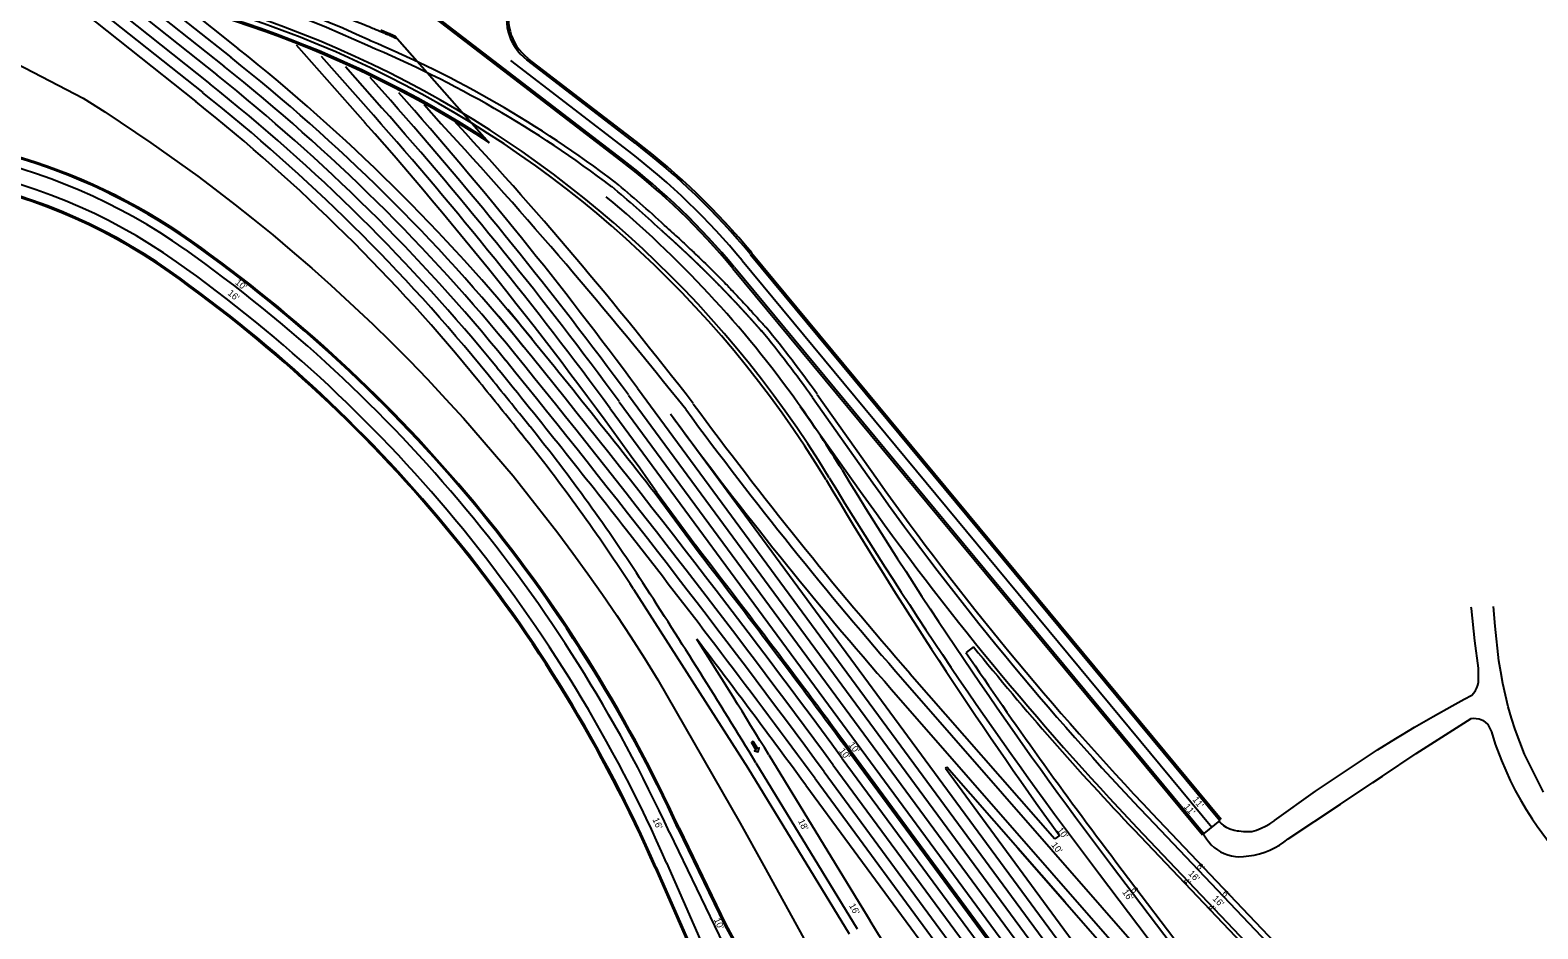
# Model space of a CAD drawing. Extents: x -5665 to 1997148, y 4 to 812485.
# Drawn here: x 1969615 to 1971217, y 796747 to 797701 of the extents above; entities that cross this region are included whole.
import ezdxf

# ---------------------------------------------------------------- set-up
doc = ezdxf.new("R2010")
doc.units = 0
for name, color, linetype in [('BR_CONCRETE', 7, 'Continuous'), ('RD_EX_RailRoad', 7, 'Continuous'), ('RD_EX_Road', 7, 'Continuous'), ('RD_PD_ALT1_TrvlWay', 7, 'Continuous'), ('RD_PD_Final_LnLine', 7, 'Continuous'), ('RD_PD_MedBWall', 7, 'Continuous'), ('RD_PD_PaveShd', 7, 'Continuous'), ('RD_SHT_TX', 7, 'Continuous'), ('RD_Sketch1', 7, 'Continuous')]:
    doc.layers.add(name, color=color, linetype=linetype)

msp = doc.modelspace()

# ---------------------------------------------------------------- linework, layer by layer
at = {"layer": 'BR_CONCRETE'}
for p, q in [((1970002.3, 797694.7), (1970102.7, 797581.1)), ((1970303.1, 796853.3), (1970352.7, 796750.9)), ((1970304.3, 796853.9), (1970353.9, 796751.4)), ((1970278.9, 796811.4), (1970358.4, 796629.6)), ((1970280, 796811.9), (1970359.6, 796630.2)), ((1970352.7, 796750.9), (1970407.3, 796650.9)), ((1970353.9, 796751.5), (1970408.4, 796651.5))]:
    msp.add_line(p, q, dxfattribs=at)
for centre, radius, start, end in [((1969482, 796626.9), 1177.6, 76.5407, 163.611), ((1969482, 796626.9), 1176, 76.5391, 163.611), ((1969482, 796626.9), 1140, 57.2466, 163.611), ((1969482, 796626.9), 1138.4, 56.954, 163.611), ((1969983.7, 797690), 10, 66.9788, 67.0375), ((1969987.6, 797699.2), 1.63, 67.0375, 67.0457), ((1969983.7, 797690), 11.6, 66.9788, 67.0375), ((1969424.5, 796964.6), 627.3, 54.7761, 131.4818), ((1969424.5, 796964.6), 626, 54.7761, 131.4818), ((1969424.5, 796964.6), 588, 54.7761, 157.246), ((1969424.5, 796964.6), 586.7, 54.7761, 157.246), ((1968885.8, 796201.6), 1560, 24.6943, 54.7761), ((1968885.8, 796201.6), 1561.3, 24.6943, 54.7761), ((1968885.8, 796201.6), 1520.7, 23.6393, 54.7761), ((1968885.8, 796201.6), 1522, 23.6393, 54.7761)]:
    msp.add_arc(centre, radius, start, end, dxfattribs=at)
for points in [[(1969930.9, 797721.6), (1969931.2, 797721.5), (1969931.5, 797721.4), (1969932, 797721.2), (1969932.3, 797721.1), (1969933.2, 797720.7), (1969935, 797720.1), (1969939.2, 797718.5), (1969947.5, 797715.4), (1969959.4, 797710.8), (1969971.2, 797706.1), (1969979.4, 797702.7), (1969983.5, 797701), (1969985.3, 797700.2), (1969986.1, 797699.8), (1969986.4, 797699.7), (1969987, 797699.5), (1969987.3, 797699.4), (1969987.6, 797699.2)], [(1969987.6, 797699.2), (1969987.9, 797699.1), (1969988.2, 797699), (1969988.8, 797698.7), (1969989.1, 797698.6), (1969989.9, 797698.2), (1969991.7, 797697.5), (1969995.8, 797695.7), (1970000.4, 797693.7), (1970003.8, 797692.2), (1970004.8, 797691.8)], [(1969988.2, 797700.7), (1969988.8, 797700.5), (1969989.4, 797700.2), (1969990.6, 797699.7), (1969991.2, 797699.5), (1969992.9, 797698.7), (1969996.4, 797697.2), (1969999.9, 797695.7), (1970002.3, 797694.7)]]:
    msp.add_open_spline(points, degree=3, dxfattribs=at)
at = {"layer": 'RD_EX_RailRoad'}
msp.add_lwpolyline([(1969600.3, 797665.2), (1969671.2, 797628.6), (1969694.2, 797613.9), (1969743.1, 797581.2), (1969793, 797545.6), (1969811, 797532.1), (1969832.7, 797515.3), (1969851.5, 797500.5), (1969872.6, 797483.3), (1969893.4, 797465.9), (1969914, 797448.1), (1969934.3, 797430), (1969979.1, 797388.5), (1969997.6, 797370.3), (1970017.4, 797350.3), (1970037, 797330.1), (1970056.2, 797309.5), (1970075.2, 797288.7), (1970127.9, 797227.7), (1970151.1, 797198.4), (1970158.9, 797188.5), (1970175.4, 797167.1), (1970191.6, 797145.5), (1970207.5, 797123.6), (1970223, 797101.5), (1970238.2, 797079.2), (1970253.1, 797056.7), (1970267.6, 797034), (1970281.8, 797011), (1970369.1, 796859), (1970394.2, 796813.5), (1970496.5, 796627.9)], dxfattribs=at)
at = {"layer": 'RD_EX_Road'}
for points in [[(1970877.7, 796861), (1970880.1, 796858.6), (1970882.7, 796856.4), (1970885.5, 796854.6), (1970888.6, 796853.1), (1970889.4, 796852.8), (1970894.1, 796851.5), (1970897, 796850.9), (1970898.9, 796850.6), (1970903.8, 796850.1), (1970908.6, 796849.9), (1970912.8, 796850.1), (1970917.8, 796851.6), (1970922.7, 796853.5), (1970927.4, 796855.7), (1970931.9, 796858.3), (1970936.2, 796861.2), (1970936.9, 796861.8), (1970980.2, 796893), (1971046.1, 796936.7), (1971046.3, 796936.8), (1971065.6, 796948.9), (1971072.8, 796953.2), (1971085.4, 796960.8), (1971105.3, 796972.3), (1971125.5, 796983.5), (1971138.4, 796990.4), (1971146.6, 796994.8), (1971148.7, 796997.1), (1971150.4, 796999.7), (1971151.8, 797002.5), (1971152.8, 797005.4), (1971153.4, 797008.5), (1971153.5, 797009.3), (1971153.4, 797023.5), (1971149.8, 797052.5), (1971146, 797086.9), (1971145.9, 797088.2)], [(1971222.4, 796891.9), (1971213, 796910.8), (1971202.4, 796932.1), (1971202.3, 796932.3), (1971192.4, 796958.4), (1971188.6, 796970.4), (1971185.1, 796982.5), (1971182.1, 796994.7), (1971179.4, 797007), (1971177.1, 797019.4), (1971175.2, 797031.2), (1971171.4, 797068.2), (1971169.4, 797088.9)], [(1970861.2, 796847.5), (1970863.8, 796843.4), (1970864.5, 796842.4), (1970866.7, 796839.4), (1970867, 796839.1), (1970869.7, 796836), (1970872.8, 796833.2), (1970876.1, 796830.7), (1970879.6, 796828.5), (1970883.3, 796826.7), (1970887.2, 796825.2), (1970891.2, 796824.1), (1970895.3, 796823.4), (1970898.1, 796823.3), (1970903.8, 796823.5), (1970909.6, 796824.1), (1970915.2, 796825.1), (1970920.9, 796826.4), (1970926.4, 796828.1), (1970931.7, 796830.3), (1970936.9, 796832.7), (1970942, 796835.5), (1970946.8, 796838.7), (1970951.4, 796842.2), (1971007, 796879.2), (1971041.3, 796902.1), (1971051.4, 796908.8), (1971087.2, 796932.8), (1971145.8, 796970), (1971148, 796970.2), (1971151.2, 796970.1), (1971154.3, 796969.7), (1971157.8, 796968.3), (1971160.7, 796966.2), (1971163.5, 796963.7), (1971167.5, 796956), (1971171.2, 796942.7), (1971177.8, 796925.4), (1971182.4, 796914.7), (1971187.3, 796904.1), (1971192.5, 796893.7), (1971198.1, 796883.5), (1971204.1, 796873.4), (1971210.4, 796863.6), (1971215.9, 796855.6), (1971244.7, 796816.7)]]:
    msp.add_lwpolyline(points, dxfattribs=at)
at = {"layer": 'RD_PD_ALT1_TrvlWay'}
for p, q in [((1970244.1, 797563.5), (1969975.7, 797769.5)), ((1969650.1, 797752.2), (1969798.3, 797634.4)), ((1969751.1, 797733.2), (1969828.2, 797672)), ((1969924.1, 797673.2), (1969979.7, 797610.4)), ((1970257.5, 797580.9), (1970142.5, 797669.2)), ((1970033.5, 797622), (1970051.7, 797601.4)), ((1970379.9, 797463.1), (1970878.6, 796861.8)), ((1970363, 797449.1), (1970861.7, 796847.8)), ((1970446.1, 797310.7), (1970510.2, 797220.3)), ((1970231.2, 797299.2), (1971104.3, 796114.9)), ((1970295.1, 797293.4), (1971172.6, 796103.1)), ((1970433, 797301.4), (1970497.1, 797211)), ((1970530.1, 797000.8), (1971103.9, 796345.5)), ((1970542.1, 797011.3), (1970931.8, 796566.4)), ((1970386, 796923), (1970493.6, 796746.7)), ((1970399.6, 796931.4), (1970507.2, 796755.1)), ((1970477.7, 796927.7), (1971068.8, 796125.9)), ((1970439.1, 796899.2), (1970686.6, 796563.5)), ((1970950.5, 796686.6), (1970791, 796854.1)), ((1970962.1, 796697.6), (1970802.6, 796865.2)), ((1970878.6, 796861.8), (1970861.7, 796847.8)), ((1970294.1, 796849.1), (1970387.5, 796656.1)), ((1970291, 796816.7), (1970370.6, 796635)), ((1970763.6, 796814.3), (1971082.9, 796393.9)), ((1970750.9, 796804.6), (1970931.8, 796566.4))]:
    msp.add_line(p, q, dxfattribs=at)
for centre, radius, start, end in [((1969482, 796626.9), 1166, 65.0802, 163.611), ((1969482, 796626.9), 1150, 31.3716, 163.611), ((1970176, 797712.9), 55, 156.731, 232.4907), ((1968569.2, 796087.2), 2024, 39.149, 51.5342), ((1969519.7, 796598.3), 1176.9, 52.7084, 67.3322), ((1968569.2, 796087.2), 1976, 39.149, 51.5342), ((1966609, 794629), 4500, 36.3977, 41.4938), ((1965926.6, 793804.9), 5606.2, 38.5451, 42.6249), ((1969424.5, 796964.6), 616, 54.7761, 150.713), ((1969794.2, 796977.3), 761, 39.6755, 52.4907), ((1969424.5, 796964.6), 600, 54.7761, 157.246), ((1969794.2, 796977.3), 739, 39.6755, 52.4907), ((1969482, 796626.9), 1178, 47.0463, 50.4066), ((1968885.8, 796201.6), 1550, 24.6902, 54.7761), ((1968885.8, 796201.6), 1534, 23.6393, 54.7761), ((1961201.8, 790089.5), 11524, 36.39766, 39.3518), ((1969482, 796626.9), 1182, 35.3463, 39.6755), ((1961201.8, 790089.5), 11476, 38.79674, 39.14904), ((1969482, 796626.9), 1166, 31.3716, 35.5262), ((1973840.1, 799899.7), 4400, 216.3977, 221.212), ((1973840.1, 799899.7), 4384, 216.3977, 221.212), ((1968587.2, 796026.8), 2000, 32.929, 38.7967), ((1974732.9, 799828.5), 5000, 211.3716, 217.212), ((1974732.9, 799828.5), 4984, 211.3716, 217.212), ((1973120.3, 799071.5), 3216, 215.3463, 223.5898), ((1973120.3, 799071.5), 3200, 215.3463, 223.5898), ((1963181.8, 792526), 8440, 31.39766, 32.92901), ((1963181.8, 792526), 8456, 31.39766, 32.37925), ((1958787.1, 788309.3), 14476, 36.3975, 37.16445), ((1972641.1, 798057.5), 2500, 210.9127, 216.3977)]:
    msp.add_arc(centre, radius, start, end, dxfattribs=at)
for points in [[(1970284.7, 797489.1), (1970285.2, 797488.6), (1970285.7, 797488.1), (1970286.2, 797487.7), (1970286.7, 797487.2), (1970287.2, 797486.8), (1970287.7, 797486.3), (1970288.2, 797485.9), (1970288.7, 797485.4), (1970289.3, 797485), (1970289.8, 797484.5), (1970290.3, 797484.1), (1970290.8, 797483.6), (1970291.3, 797483.1), (1970291.8, 797482.7), (1970292.3, 797482.2), (1970292.8, 797481.8), (1970293.3, 797481.3), (1970293.8, 797480.9), (1970294.3, 797480.4), (1970294.8, 797480), (1970295.3, 797479.5), (1970295.9, 797479), (1970296.4, 797478.6), (1970296.9, 797478.1), (1970297.4, 797477.7), (1970297.9, 797477.2), (1970298.4, 797476.7), (1970298.9, 797476.3), (1970299.4, 797475.8), (1970299.9, 797475.4), (1970300.4, 797474.9), (1970300.9, 797474.4), (1970301.4, 797474), (1970301.9, 797473.5), (1970302.4, 797473), (1970302.9, 797472.6), (1970303.4, 797472.1), (1970303.9, 797471.7), (1970304.4, 797471.2), (1970304.9, 797470.7), (1970305.4, 797470.3), (1970305.9, 797469.8), (1970306.4, 797469.3), (1970306.9, 797468.9), (1970307.4, 797468.4), (1970307.9, 797467.9), (1970308.4, 797467.5), (1970308.9, 797467), (1970309.4, 797466.5), (1970309.9, 797466.1), (1970310.4, 797465.6), (1970310.9, 797465.1), (1970311.4, 797464.7), (1970311.9, 797464.2), (1970312.4, 797463.7), (1970312.9, 797463.3), (1970313.4, 797462.8), (1970313.9, 797462.3), (1970314.4, 797461.9), (1970314.9, 797461.4), (1970315.4, 797460.9), (1970315.9, 797460.5), (1970316.4, 797460), (1970316.9, 797459.5), (1970317.4, 797459), (1970317.9, 797458.6), (1970318.4, 797458.1), (1970318.9, 797457.6), (1970319.4, 797457.2), (1970319.9, 797456.7), (1970320.3, 797456.2), (1970320.8, 797455.7), (1970321.3, 797455.3), (1970321.8, 797454.8)], [(1970321.8, 797454.8), (1970322.3, 797454.3), (1970322.8, 797453.8), (1970323.3, 797453.4), (1970323.8, 797452.9), (1970324.3, 797452.4), (1970324.8, 797451.9), (1970325.3, 797451.5), (1970325.8, 797451), (1970326.3, 797450.5), (1970326.7, 797450), (1970327.2, 797449.6), (1970327.7, 797449.1), (1970328.2, 797448.6), (1970328.7, 797448.1), (1970329.2, 797447.6), (1970329.7, 797447.2), (1970330.2, 797446.7), (1970330.7, 797446.2), (1970331.1, 797445.7), (1970331.6, 797445.2), (1970332.1, 797444.8), (1970332.6, 797444.3), (1970333.1, 797443.8), (1970333.6, 797443.3), (1970334.1, 797442.8), (1970334.5, 797442.4), (1970335, 797441.9), (1970335.5, 797441.4), (1970336, 797440.9), (1970336.5, 797440.4), (1970337, 797439.9), (1970337.5, 797439.5), (1970337.9, 797439), (1970338.4, 797438.5), (1970338.9, 797438), (1970339.4, 797437.5), (1970339.9, 797437), (1970340.4, 797436.6), (1970340.8, 797436.1), (1970341.3, 797435.6), (1970341.8, 797435.1), (1970342.3, 797434.6), (1970342.8, 797434.1), (1970343.2, 797433.6), (1970343.7, 797433.2), (1970344.2, 797432.7), (1970344.7, 797432.2), (1970345.2, 797431.7), (1970345.6, 797431.2), (1970346.1, 797430.7), (1970346.6, 797430.2), (1970347.1, 797429.7), (1970347.6, 797429.3), (1970348, 797428.8), (1970348.5, 797428.3), (1970349, 797427.8), (1970349.5, 797427.3), (1970349.9, 797426.8), (1970350.4, 797426.3), (1970350.9, 797425.8), (1970351.4, 797425.3), (1970351.8, 797424.8), (1970352.3, 797424.3), (1970352.8, 797423.9), (1970353.3, 797423.4), (1970353.7, 797422.9), (1970354.2, 797422.4), (1970354.7, 797421.9), (1970355.2, 797421.4), (1970355.6, 797420.9), (1970356.1, 797420.4), (1970356.6, 797419.9), (1970357.1, 797419.4), (1970357.5, 797418.9)], [(1970357.5, 797418.9), (1970358, 797418.4), (1970358.5, 797417.9), (1970359, 797417.4), (1970359.4, 797416.9), (1970359.9, 797416.4), (1970360.4, 797415.9), (1970360.8, 797415.4), (1970361.3, 797414.9), (1970361.8, 797414.4), (1970362.2, 797413.9), (1970362.7, 797413.4), (1970363.2, 797412.9), (1970363.7, 797412.5), (1970364.1, 797412), (1970364.6, 797411.5), (1970365.1, 797411), (1970365.5, 797410.5), (1970366, 797410), (1970366.5, 797409.5), (1970366.9, 797409), (1970367.4, 797408.5), (1970367.9, 797407.9), (1970368.3, 797407.4), (1970368.8, 797406.9), (1970369.3, 797406.4), (1970369.7, 797405.9), (1970370.2, 797405.4), (1970370.7, 797404.9), (1970371.1, 797404.4), (1970371.6, 797403.9), (1970372, 797403.4), (1970372.5, 797402.9), (1970373, 797402.4), (1970373.4, 797401.9), (1970373.9, 797401.4), (1970374.4, 797400.9), (1970374.8, 797400.4), (1970375.3, 797399.9), (1970375.7, 797399.4), (1970376.2, 797398.9), (1970376.7, 797398.4), (1970377.1, 797397.9), (1970377.6, 797397.4), (1970378, 797396.9), (1970378.5, 797396.3), (1970379, 797395.8), (1970379.4, 797395.3), (1970379.9, 797394.8), (1970380.3, 797394.3), (1970380.8, 797393.8), (1970381.3, 797393.3), (1970381.7, 797392.8), (1970382.2, 797392.3), (1970382.6, 797391.8), (1970383.1, 797391.3), (1970383.5, 797390.7), (1970384, 797390.2), (1970384.5, 797389.7), (1970384.9, 797389.2), (1970385.4, 797388.7), (1970385.8, 797388.2), (1970386.3, 797387.7), (1970386.7, 797387.2), (1970387.2, 797386.6), (1970387.6, 797386.1), (1970388.1, 797385.6), (1970388.5, 797385.1), (1970389, 797384.6), (1970389.5, 797384.1), (1970389.9, 797383.6), (1970390.4, 797383), (1970390.8, 797382.5), (1970391.7, 797381.5)]]:
    msp.add_spline(points, degree=3, dxfattribs=at)
at = {"layer": 'RD_PD_Final_LnLine'}
for p, q in [((1969680.7, 797743.2), (1969805.8, 797643.8)), ((1969725.9, 797737.9), (1969820.7, 797662.6)), ((1969719.2, 797727.9), (1969813.3, 797653.2)), ((1969949.9, 797662.2), (1969988.6, 797618.3)), ((1970250.8, 797572.2), (1970125.4, 797668.5)), ((1969975.8, 797650.9), (1969997.6, 797626.3)), ((1970006.2, 797634.7), (1970006.6, 797634.2)), ((1970371.4, 797456.1), (1970870.2, 796854.8)), ((1970260.1, 797320.6), (1971160.7, 796098.9)), ((1970240.8, 797306.3), (1971130.9, 796098.9)), ((1970250.5, 797313.4), (1971142.9, 796102.8)), ((1970468.1, 796920.6), (1971049.6, 796131.7)), ((1970448.7, 796906.3), (1970838.1, 796378.1)), ((1970458.4, 796913.4), (1971024.8, 796145.1))]:
    msp.add_line(p, q, dxfattribs=at)
for centre, radius, start, end in [((1968569.2, 796087.2), 2012, 39.149, 51.5342), ((1968569.2, 796087.2), 1988, 39.149, 51.5342), ((1968569.2, 796087.2), 2000, 39.149, 51.5342), ((1966609, 794629), 4524, 36.3977, 41.4938), ((1966609, 794629), 4536, 36.3977, 41.4938), ((1966609, 794629), 4512, 36.3977, 41.4938), ((1969794.2, 796977.3), 750, 39.6755, 52.4907), ((1969482, 796626.9), 1166, 35.5262, 50.2894), ((1961201.8, 790089.5), 11500, 36.39766, 39.14904), ((1961201.8, 790089.5), 11512, 36.39766, 39.14904), ((1961201.8, 790089.5), 11488, 38.04902, 39.14904), ((1961201.8, 790089.5), 11488, 36.39766, 38.04902)]:
    msp.add_arc(centre, radius, start, end, dxfattribs=at)
at = {"layer": 'RD_PD_MedBWall'}
for p, q in [((1970320.6, 797152.2), (1970279, 797208.9)), ((1970280.4, 797210.3), (1970322, 797153.7)), ((1970485.8, 796933.6), (1971046.6, 796172.9)), ((1970487.4, 796934.8), (1971048.2, 796174.1))]:
    msp.add_line(p, q, dxfattribs=at)
for radius in [11534, 11536]:
    msp.add_arc((1961201.8, 790089.5), radius, 36.39766, 37.7603, dxfattribs=at)
at = {"layer": 'RD_PD_PaveShd'}
for p, q in [((1970242.9, 797561.9), (1969974.5, 797767.9)), ((1969627.5, 797754.8), (1969790.9, 797625)), ((1969781.4, 797724.4), (1969835.6, 797681.4)), ((1969897.6, 797685.1), (1969970.7, 797602.4)), ((1970258.7, 797582.5), (1970143.7, 797670.8)), ((1970381.4, 797464.4), (1970880.2, 796863.1)), ((1970361.4, 797447.8), (1970860.2, 796846.5)), ((1970451, 797314.1), (1970515.1, 797223.7)), ((1970255.8, 797107.4), (1970377.4, 796917.8)), ((1970617.1, 797046.1), (1970609.1, 797040.2)), ((1970549.6, 797017.9), (1970703.6, 796842.1)), ((1970487.4, 796934.8), (1971048.2, 796174.1)), ((1970377.4, 796917.8), (1970485, 796741.5)), ((1970587.2, 796917.4), (1970588.8, 796918.5)), ((1970587.2, 796917.4), (1970691.5, 796775.9)), ((1970714.4, 796775.1), (1970588.8, 796918.5)), ((1970966.4, 796701.7), (1970806.9, 796869.3)), ((1970708.3, 796845.8), (1970703.6, 796842.1)), ((1970947.6, 796683.8), (1970788.1, 796851.4)), ((1970664.3, 796832.4), (1971056.8, 796384.2)), ((1970768.4, 796817.9), (1971000.9, 796511.8)), ((1970691.5, 796775.9), (1971027.6, 796319.9))]:
    msp.add_line(p, q, dxfattribs=at)
for points in [[(1970326, 797459.1), (1970326, 797459.1), (1970326, 797459.1)], [(1970361.9, 797423.1), (1970361.9, 797423.1), (1970361.9, 797423.1)]]:
    msp.add_lwpolyline(points, dxfattribs=at)
for centre, radius, start, end in [((1969482, 796626.9), 1172, 65.0633, 163.611), ((1969482, 796626.9), 1146, 31.3716, 163.611), ((1970176, 797712.9), 53, 156.731, 232.4907), ((1969519.7, 796598.3), 1182.9, 52.7084, 67.3322), ((1968569.2, 796087.2), 2036, 39.149, 51.5342), ((1968569.2, 796087.2), 1964, 39.149, 51.5342), ((1966880.6, 794650.8), 4343.5, 37.6555, 42.9344), ((1966609, 794629), 4488, 35.1073, 41.4938), ((1969794.2, 796977.3), 763, 39.6755, 52.4907), ((1969794.2, 796977.3), 737, 39.6755, 52.4907), ((1969482, 796626.9), 1184, 47.0463, 50.4124), ((1961201.8, 790089.5), 11536, 38.10788, 39.3518), ((1969482, 796626.9), 1188, 35.3463, 39.6755), ((1961201.8, 790089.5), 11464, 38.79674, 39.14904), ((1973840.1, 799899.7), 4374, 216.3977, 221.212), ((1968587.2, 796026.8), 1988, 32.929, 38.7967), ((1974766.1, 799779.8), 5007.3, 210.6987, 215.8694), ((1973120.3, 799071.5), 3194, 215.3463, 223.5898), ((1973120.3, 799071.5), 3220, 218.9765, 223.5898), ((1974732.9, 799828.5), 4978, 214.0642, 217.212)]:
    msp.add_arc(centre, radius, start, end, dxfattribs=at)
for points in [[(1970288.6, 797493.5), (1970295, 797487.9), (1970304.4, 797479.4), (1970315.3, 797469.3), (1970320.6, 797464.2), (1970323.3, 797461.7), (1970324.5, 797460.6), (1970325.2, 797459.8), (1970325.6, 797459.5), (1970326, 797459.1)], [(1970326, 797459.1), (1970332.1, 797453.2), (1970341.2, 797444.3), (1970351.6, 797433.7), (1970356.7, 797428.4), (1970359.3, 797425.7), (1970360.4, 797424.6), (1970361.1, 797423.8), (1970361.5, 797423.4), (1970361.9, 797423.1)], [(1970361.9, 797423.1), (1970367.7, 797416.9), (1970376.4, 797407.6), (1970386.4, 797396.6), (1970391.3, 797391), (1970393.4, 797388.6), (1970394.5, 797387.4), (1970394.8, 797387), (1970395.5, 797386.3), (1970395.9, 797385.9), (1970396.2, 797385.5)]]:
    msp.add_open_spline(points, degree=3, dxfattribs=at)
at = {"layer": 'RD_SHT_TX'}
msp.add_lwpolyline([(1970383.1, 796945.7), (1970381.1, 796944.4), (1970385.8, 796936.6), (1970384.4, 796935.8), (1970388.3, 796934.8), (1970389.3, 796938.7), (1970387.9, 796937.9)], close=True, dxfattribs=at)
at = {"layer": 'RD_Sketch1'}
msp.add_line((1970004.8, 797691.8), (1970020.4, 797674.2), dxfattribs=at)

# ---------------------------------------------------------------- texts
at = {"layer": 'RD_SHT_TX'}
for s, rotation, p in [("10'", 320.6013, (1969832.2, 797431.9)), ("16'", 320.6013, (1969824.2, 797420.5)), ("10'", 307.533, (1970473.8, 796935.4)), ("10'", 307.533, (1970483.9, 796941.9)), ("11'", 308.2407, (1970849.3, 796883.7)), ("11'", 310.1671, (1970840.1, 796876.1)), ("16'", 293.42, (1970275.9, 796862.9)), ("18'", 296.256, (1970430.4, 796861.2)), ("10'", 307.5314, (1970705.3, 796851.2)), ("10'", 307.5314, (1970699.2, 796835.6)), ("16'", 313.9148, (1970844.7, 796804.9)), ("6'", 313.7402, (1970853.4, 796812.4)), ("6'", 305.3319, (1970783.9, 796788.1)), ("4'", 313.7155, (1970839, 796796.8)), ("16'", 299.71, (1970484.6, 796771.4)), ("16'", 305.3319, (1970774.7, 796785.6)), ("16'", 313.9148, (1970870.5, 796778.2)), ("6'", 315.4353, (1970880.4, 796783.4)), ("10'", 294.0609, (1970341.1, 796756.5)), ("4'", 313.7155, (1970865.2, 796768.8))]:
    msp.add_text(s, height=7, rotation=rotation, dxfattribs=at).set_placement(p)

doc.saveas('drawing.dxf')
